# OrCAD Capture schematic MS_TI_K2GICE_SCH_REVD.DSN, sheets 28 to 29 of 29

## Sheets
28 P28_POWER ORING & OVP: size C; title: POWER ORING & OVP CIRCUIT
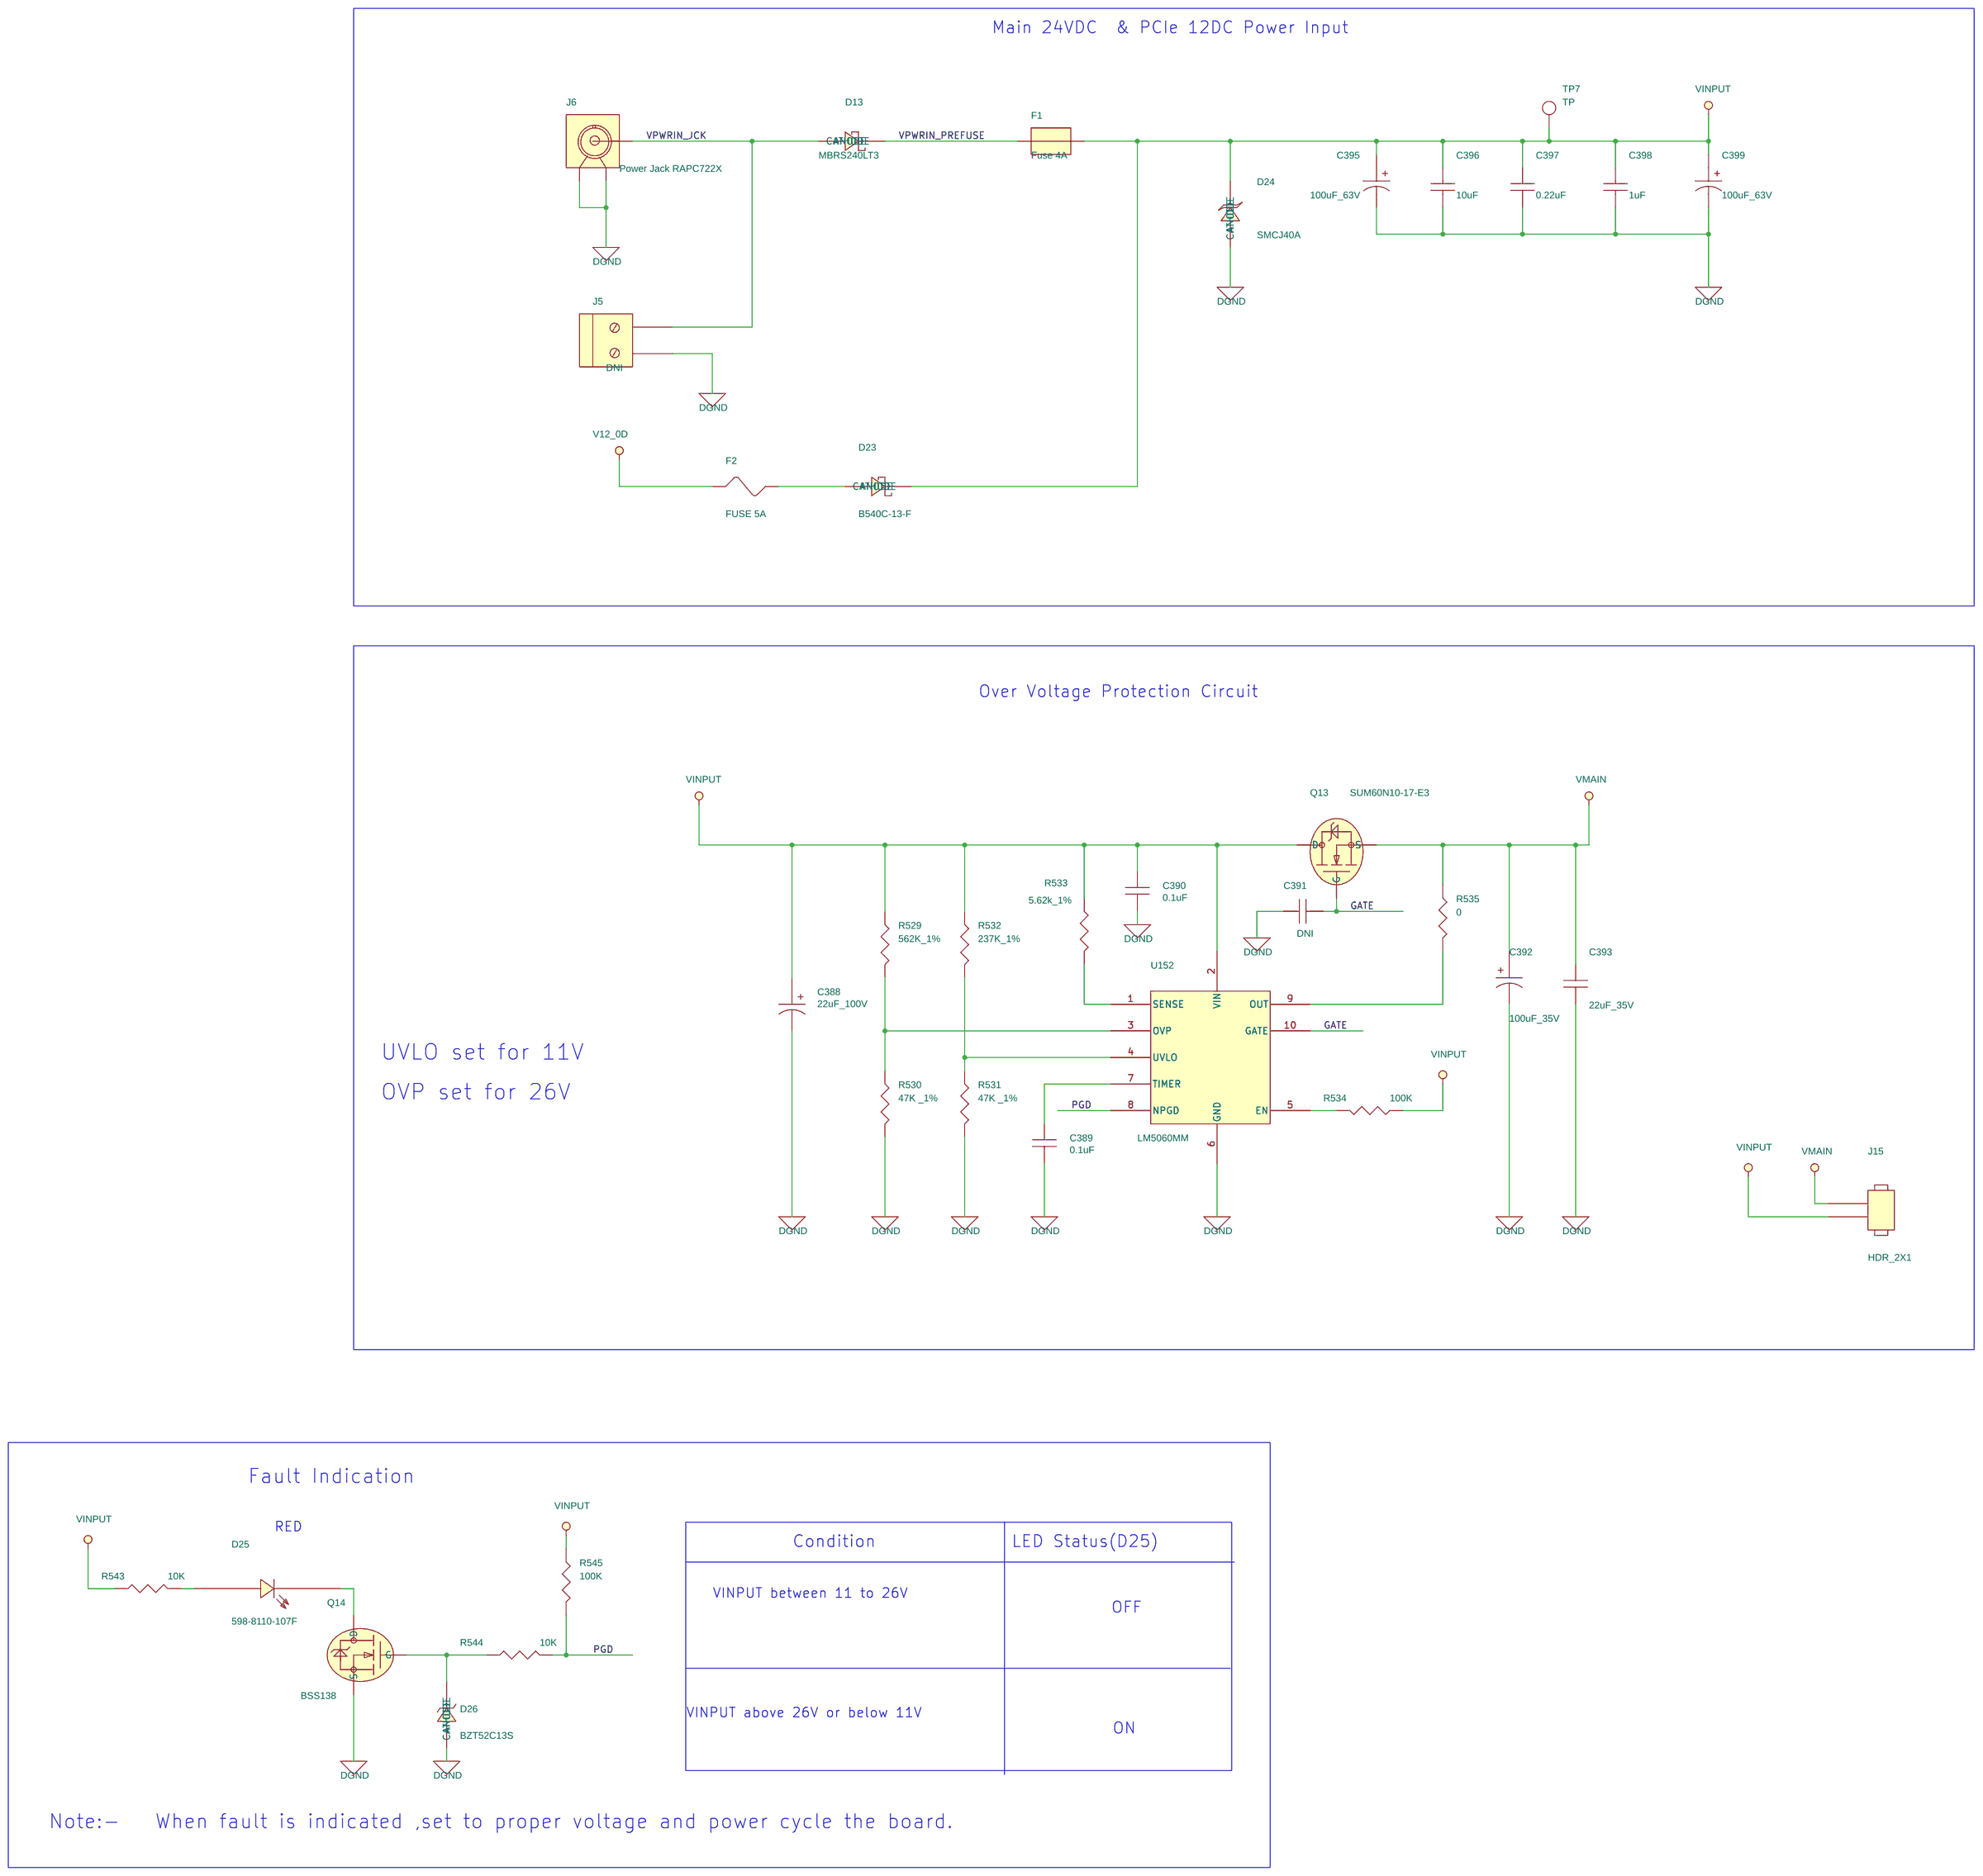
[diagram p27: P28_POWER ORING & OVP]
29 P29_HARDWARE SCHEMATICS: size C; title: HARDWARE SCHEMATICS
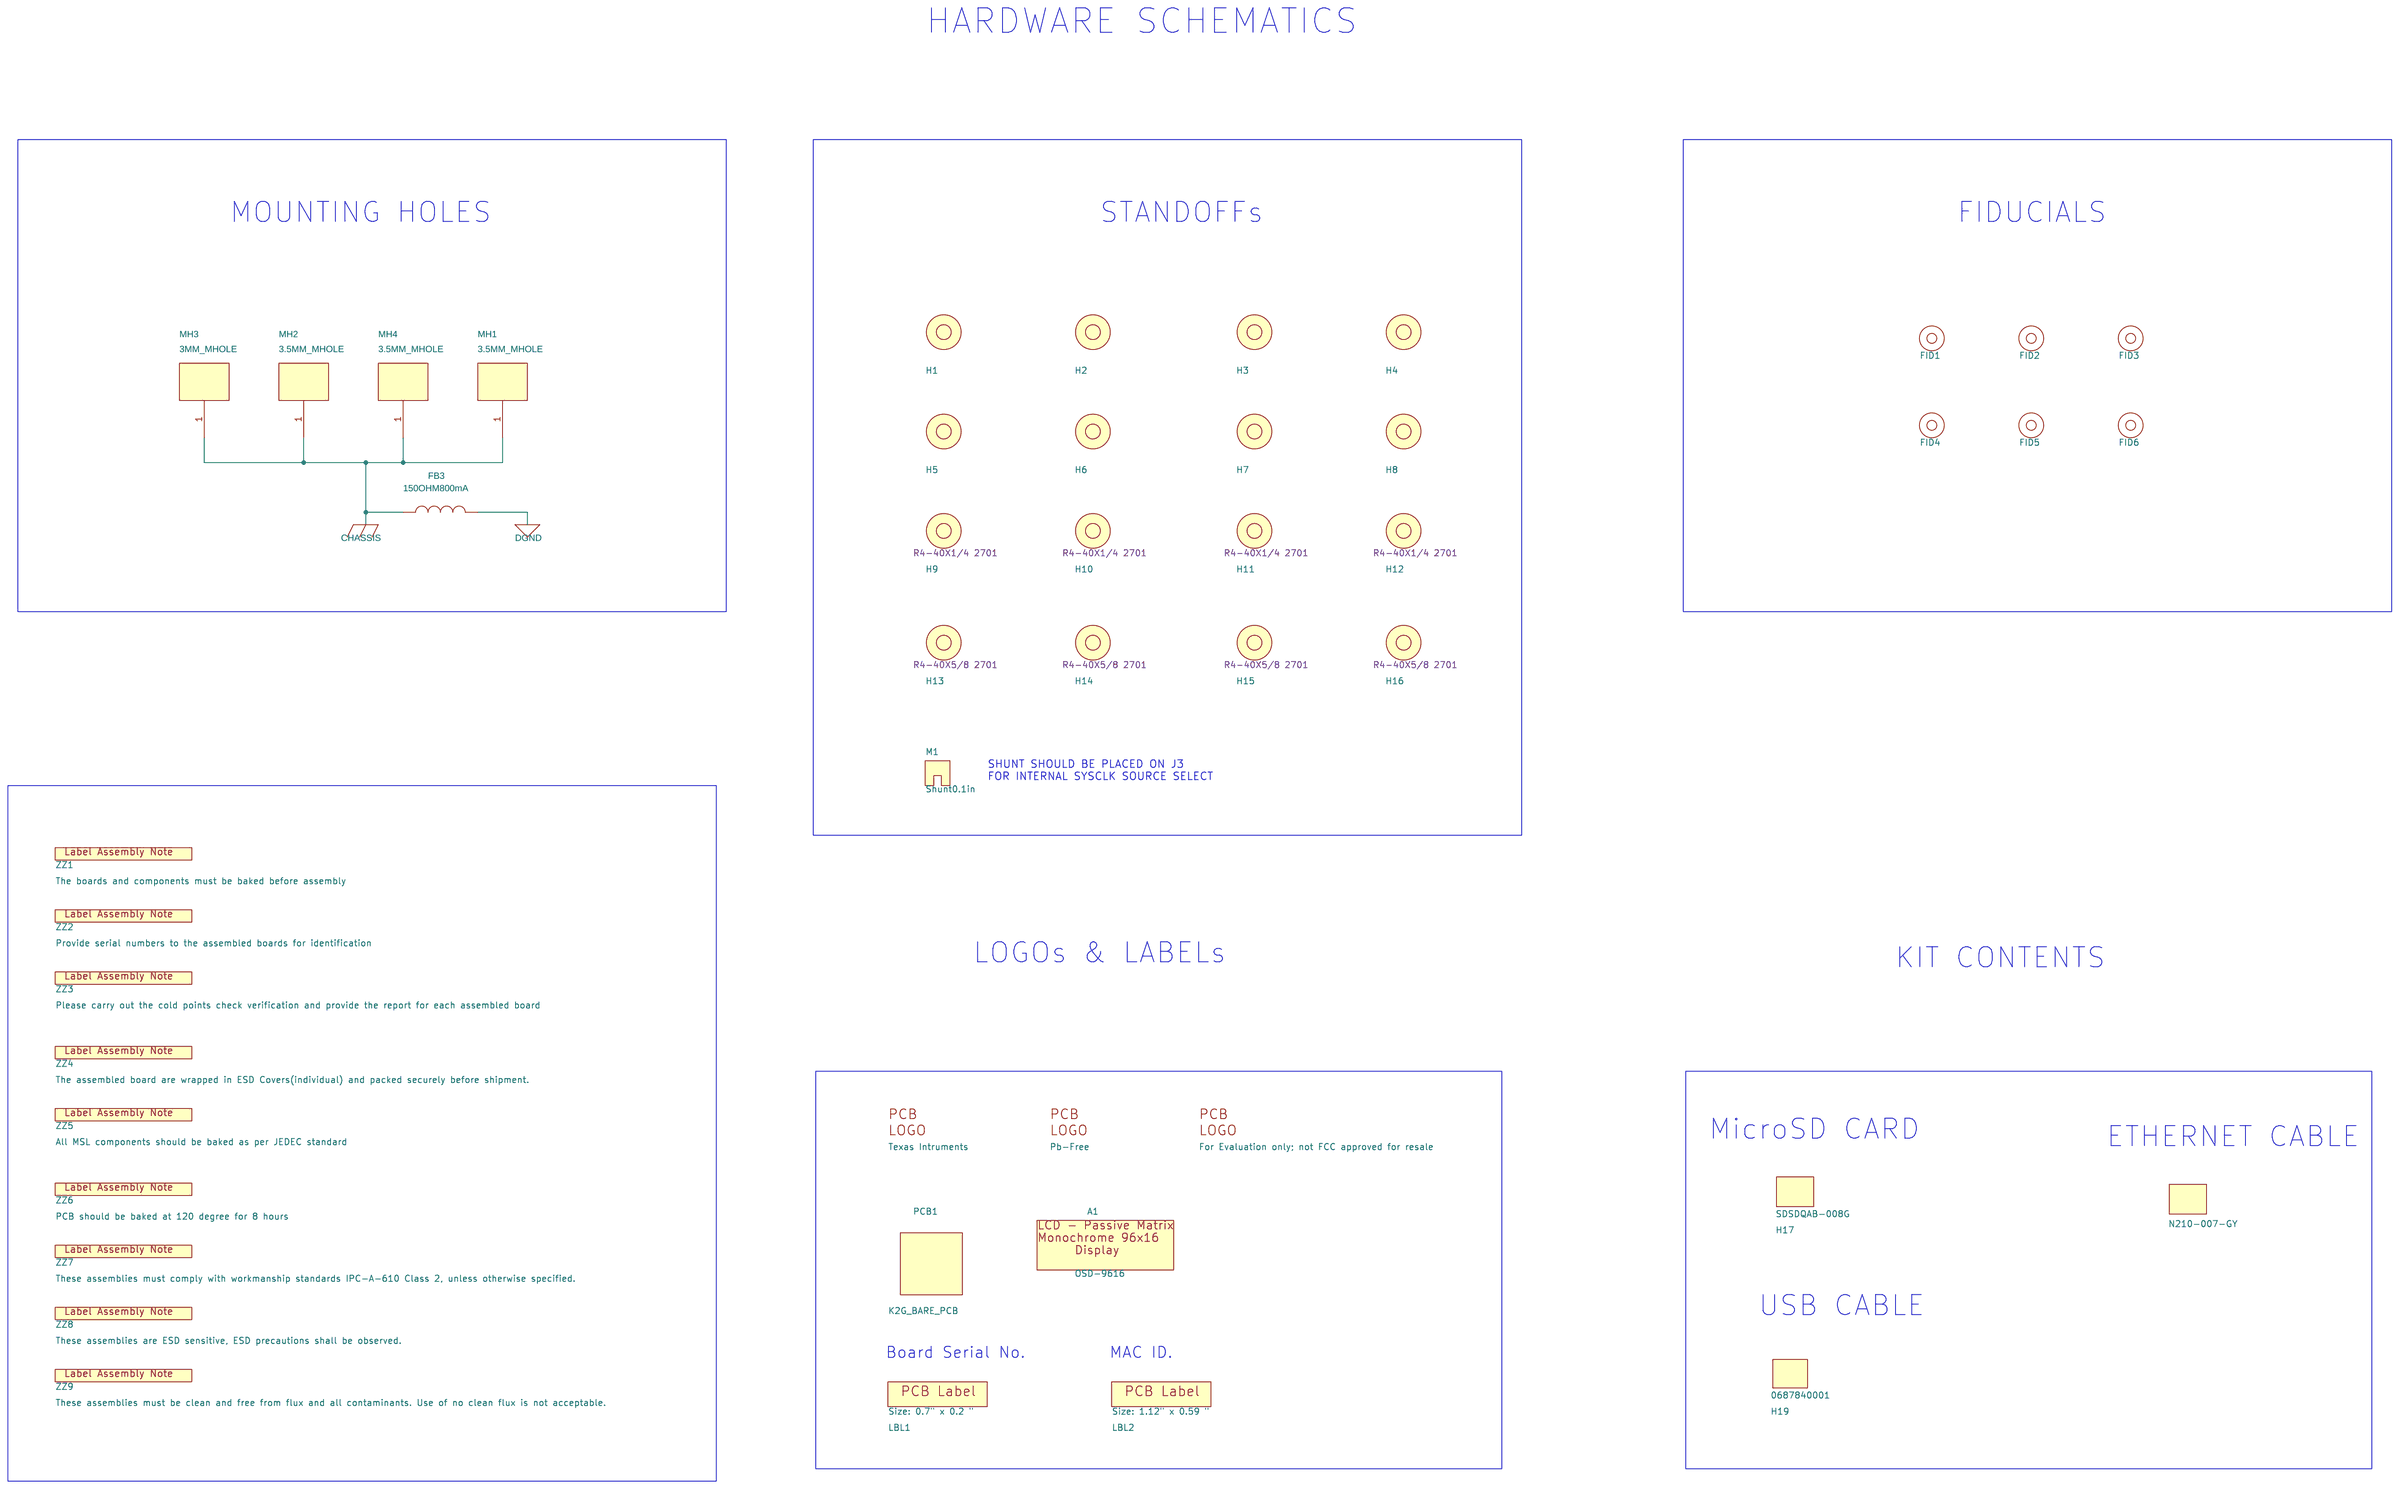
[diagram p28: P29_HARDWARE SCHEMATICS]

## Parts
sheet P28_POWER ORING & OVP
C388  22uF_100V  [CAPAE_GCASE]
C389  0.1uF  [CAP0603]
C390  0.1uF  [CAP0603]
C391  DNI  [SM-7351-CAP-0402]
C392  100uF_35V  [CAPAE_D8CASE]
C393  22uF_35V  [CAP0805]
C395  100uF_63V  [CAPAE_CASE1213]
C396  10uF  [CAP1210]
C397  0.22uF  [CAP1206]
C398  1uF  [CAP1206]
C399  100uF_63V  [CAPAE_CASE1213]
D13  MBRS240LT3  [DIO_SMB]
D23  B540C-13-F  [DIO_SMC]
D24  SMCJ40A  [DIO_SMC]
D25  598-8110-107F  [LED_0805]
D26  BZT52C13S  [DIO_SOD323]
F1  Fuse 4A  [smdfuseblk]
F2  FUSE 5A  [FUSE-RGEF600]
J5  DNI  [conn_osttc02]
J6  Power Jack RAPC722X  [RAPC712]
J15  HDR_2X1  [HDR_2X1_100_S_T]
Q13  SUM60N10-17-E3  [D2PAK-3]
Q14  BSS138  [TO_SOT23-123]
R529  562K_1%  [RES0402]
R530  47K _1%  [RES0402]
R531  47K _1%  [RES0402]
R532  237K_1%  [RES0402]
R533  5.62k_1%  [RES0603]
R534  100K  [RES0402]
R535  0  [RES0402]
R543  10K  [RES1206]
R544  10K  [SM-7351-RES-0402]
R545  100K  [SM-7351-RES-0402]
TP7  TP  [TH_TP_5002]
U152  LM5060MM  [MSOP10_19-68_120X120]
sheet P29_HARDWARE SCHEMATICS
A1  OSD-9616  [-]
FB3  150OHM800mA  [sm-7351-ind-0805]
FID1  Fiducial  [Fiducial10-20]
FID2  Fiducial  [Fiducial10-20]
FID3  Fiducial  [Fiducial10-20]
FID4  Fiducial  [Fiducial10-20]
FID5  Fiducial  [Fiducial10-20]
FID6  Fiducial  [Fiducial10-20]
H1  3482  [Keystone_1902C]
H2  3482  [Keystone_1902C]
H3  3482  [Keystone_1902C]
H4  3482  [Keystone_1902C]
H5  720  [Keystone_1902C]
H6  720  [Keystone_1902C]
H7  720  [Keystone_1902C]
H8  720  [Keystone_1902C]
H9  R4-40X1/4 2701  [Keystone_1902C]
H10  R4-40X1/4 2701  [Keystone_1902C]
H11  R4-40X1/4 2701  [Keystone_1902C]
H12  R4-40X1/4 2701  [Keystone_1902C]
H13  R4-40X5/8 2701  [Keystone_1902C]
H14  R4-40X5/8 2701  [Keystone_1902C]
H15  R4-40X5/8 2701  [Keystone_1902C]
H16  R4-40X5/8 2701  [Keystone_1902C]
H17  SDSDQAB-008G  [Keystone_1902C]
H18  N210-007-GY  [Keystone_1902C]
H19  0687840001  [Keystone_1902C]
LBL1  Size: 0.7" x 0.2 "  [Label_650x200]
LBL2  Size: 1.12" x 0.59 "  [Label_650x200]
LOGO1  Texas Intruments  [TI_Stacked_Overlay_Small]
LOGO2  Pb-Free  [Pb-Free_Overlay_Small]
LOGO3  For Evaluation only; not FCC approved for resale  [FCC_disclaimer]
M1  Shunt0.1in  [DNP]
MH1  3.5MM_MHOLE  [MH163X138PL]
MH2  3.5MM_MHOLE  [MH163X138PL]
MH3  3MM_MHOLE  [MH163X138PL]
MH4  3.5MM_MHOLE  [MH163X138PL]
PCB1  K2G_BARE_PCB  [-]
ZZ1  The boards and components must be baked before assembly  [AssemblyNoteLabel]
ZZ2  Provide serial numbers to the assembled boards for identification  [AssemblyNoteLabel]
ZZ3  Please carry out the cold points check verification and provide the report for each assembled board  [AssemblyNoteLabel]
ZZ4  The assembled board are wrapped in ESD Covers(individual) and packed securely before shipment.  [AssemblyNoteLabel]
ZZ5  All MSL components should be baked as per JEDEC standard  [AssemblyNoteLabel]
ZZ6  PCB should be baked at 120 degree for 8 hours  [AssemblyNoteLabel]
ZZ7  These assemblies must comply with workmanship standards IPC-A-610 Class 2, unless otherwise specified.  [AssemblyNoteLabel]
ZZ8  These assemblies are ESD sensitive, ESD precautions shall be observed.  [AssemblyNoteLabel]
ZZ9  These assemblies must be clean and free from flux and all contaminants. Use of no clean flux is not acceptable.  [AssemblyNoteLabel]

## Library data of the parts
C388 = CAP_POL: Crtd /date: VASANTHA/170516; DescriptiveText: CAP ELECTROLYTIC 22uF 100V 20% GCASE_103103; Mfr: PANASONIC-ECG; MfrNum: EEE-HA2A220P; Mistral part number: NSPN00373; Part_type: CAPACITORS\ELECTROLYTIC
C389 C390 = CAP: Crtd /date: VASANTHA/170516; DescriptiveText: CAP CERAMIC 0.1uF 100V 10% X7R 0603; Mfr: YAGEO AMERICA; MfrNum: CC0603KRX7R0BB104; Mistral part number: NSPN00374; Part_type: CAPACITORS\CERAMIC
C391 = 1C_0.01uFCapacitor16V10%0402
C392 = CAP_POL: Crtd /date: VASANTHA/170516; DescriptiveText: CAP ELECTROLYTIC 100uF 35V 20% D8CASE_6666; Mfr: PANASONIC-ECG; MfrNum: EEE-FK1V101XP; Mistral part number: NSPN00370; Part_type: CAPACITORS\ELECTROLYTIC
C393 = CAP: Crtd /date: VASANTHA/170516; DescriptiveText: CAP CERAMIC 22uF 35V 20% X5R 0805; Mfr: TDK CORPORATION; MfrNum: C2012X5R1V226M125AC; Mistral part number: NSPN00375; Part_type: CAPACITORS\CERAMIC
C395 C399 = CAP_POL: Crtd /date: VASANTHA/170516; DescriptiveText: CAP ELECTROLYTIC 100uF 63V 20% RADIAL CAN CASE1213; Mfr: VISHAY; MfrNum: MAL214699806E3; Mistral part number: NSPN00372; Part_type: CAPACITORS\ELECTROLYTIC
C396 = CAP: Crtd /date: VASANTHA/170516; DescriptiveText: CAP CERAMIC 10uF 63V 10% X7R 1210; Mfr: MURATA; MfrNum: GRM32ER71J106KA12L; Mistral part number: NSPN00367; Part_type: CAPACITORS\CERAMIC
C397 = CAP: Crtd /date: VASANTHA/170516; DescriptiveText: CAP CERAMIC 0.22uF 100V 10% X7R 1206; Mfr: MURATA; MfrNum: GRM31MR72A224KA01L; Mistral part number: NSPN00369; Part_type: CAPACITORS\CERAMIC
C398 = CAP: Crtd /date: VASANTHA/170516; DescriptiveText: CAP CERAMIC 1uF 100V 10% X7R 1206; Mfr: TDK CORPORATION; MfrNum: C3216X7R2A105K160AA; Mistral part number: NSPN00371; Part_type: CAPACITORS\CERAMIC
D13 = DIODE_SCHOTTKY: DIODE SCHOTTKY 40V 2A SMB; Crtd /date: VASANTHA/100616; Custom_Duty: 15%; Customs_HS_Code: 85412900; DescriptiveText: DIODE SCHOTTKY 40V 2A SMB; Distributor_name: DIGIKEY; Distributor_part_number: MBRS240LT3OSTR-ND; Height: 2.62MM; Mfr: ON SEMICONDUCTOR; MfrNum: MBRS240LT3G; Mfr_name: ON SEMICONDUCTOR; Mfr_part_number: MBRS240LT3G; Mistral Part No: 130009030216; Mistral part number: NSPN00396; Package: SMB; Part_type: DIODE\SCHOTTKY; Project: G4SLIM; Voltage: 40V; Datasheet: Y:\MIS_DATABASE\DATASHEETS\DISCRETES\DIODES\B5.PDF
D23 = DIODE_SCHOTTKY: Crtd /date: VASANTHA/170516; DescriptiveText: DIODE SCHOTTKY 40V 5A SMC; Mfr: DIODES INC; Mistral part number: NSPN00377; Part_type: DIODE\SCHOTTKY
D24 = DIODE_TVS: Crtd /date: VASANTHA/170516; DescriptiveText: DIODE TVS 1500W 40V SMC; Mfr: BOURNS; Mistral part number: NSPN00378; Part_type: DIODE\TVS
D25 = LED_598-8170-107F: Crtd /date: VASANTHA/170516; DescriptiveText: LED ALINGAP RED CLEAR 0805 SMD; Mfr: DIALIGHT; MfrNum: 5988110107F; Mistral part number: NSPN00379; Part_type: OPTO\LED
D26 = DIODE_ZENER: Crtd /date: VASANTHA/170516; DescriptiveText: DIODE ZENER 13V 200mW SOD323; Mfr: DIODES INC; MfrNum: BZT52C13S-7-F; Mistral part number: NSPN00376; Part_type: DIODE\ZENER
F1 = 1P_Fuse_4A
F2 = Fuse_RGEF600-2
J5 = 2C_Conn_LeadScrewDown_2pin
J6 = 2J_Conn_PwrJack_RAPC722
J15 = HEADER_2X1: Crtd /date: VASANTHA/170516; DescriptiveText: CON HDR 2X1 2.54MM PITCH ST TH; Mfr: MOLEX; MfrNum: 0022032021; Mistral part number: NSPN00390; Part_type: CONNECTOR\HEADER
Q13 = MOSFET_IRFZ24NS: Crtd /date: VASANTHA/170516; DescriptiveText: IC POWER MOSFET N-CHANNEL D2PAK; Mfr: VISHAY; Mistral part number: NSPN00388; Part_type: ICS\POWER\MOSFET
Q14 = MOSFET_BSS138: Crtd /date: VASANTHA/170516; DescriptiveText: IC MOSFET N-CHANNEL 50V 200mA SOT23-3; Mfr: DIODES INC; MfrNum: BSS138-7-F; Mistral part number: NSPN00386; Part_type: ICS\POWER\MOSFET
R529 = RESISTOR: Crtd /date: VASANTHA/170516; DescriptiveText: RES 562K 1/16W 1% 0402; Mfr: PANASONIC-ECG; MfrNum: ERJ-2RKF5623X; Mistral part number: NSPN00360; Part_type: RESISTORS\FIXED
R530 R531 = RESISTOR: Crtd /date: VASANTHA/170516; DescriptiveText: RES 47K 1/16W 1% 0402; Mfr: YAGEO AMERICA; MfrNum: RC0402FR-0747KL; Mistral part number: NSPN00358; Part_type: RESISTORS\FIXED
R532 = RESISTOR: Crtd /date: VASANTHA/170516; DescriptiveText: RES 237K 1/16W 1% 0402; Mfr: STACKPOLE ELECTRONICS; MfrNum: RMCF0402FT237K; Mistral part number: NSPN00365; Part_type: RESISTORS\FIXED
R533 = RESISTOR: Crtd /date: VASANTHA/170516; DescriptiveText: RES 5.62K 1/10W 1% 0603; Mfr: VISHAY; MfrNum: CRCW06035K62FKEA; Mistral part number: NSPN00362; Part_type: RESISTORS\FIXED
R534 = RESISTOR: Crtd /date: VASANTHA/170516; DescriptiveText: RES 100K 1/16W 5% 0402; Mfr: PANASONIC-ECG; MfrNum: ERJ-2GEJ104X; Mistral part number: NSPN00355; Part_type: RESISTORS\FIXED
R535 = RESISTOR: Crtd /date: VASANTHA/170516; DescriptiveText: RES 0E 1/10W 5% 0402; Mfr: PANASONIC-ECG; MfrNum: ERJ-2GE0R00X; Mistral part number: NSPN00364; Part_type: RESISTORS\FIXED
R543 = RESISTOR: Crtd /date: VASANTHA/170516; DescriptiveText: RES 10K 2/3W 5% 1206; Mfr: PANASONIC; MfrNum: ERJ-P08J103V; Mistral part number: NSPN00366; Part_type: RESISTORS\FIXED
R544 = 1R_10KOhmResistor1_16W0402
R545 = 1R_100KOhmResistor1_16W0402
TP7 = 2H_TestPointThroughHole
U152 = LM5060_MSOP10: Crtd /date: VASANTHA/170516; DescriptiveText: IC CONTROLLER HIGH-SIDE PROTECTION VSSOP10; Mfr: TEXAS INSTRUMENTS; MfrNum: LM5060MM/NOPB; Mistral part number: NSPN00387; Part_type: ICS\POWER\MANAGEMENT
A1 = LCD_OSD9616P0899-10: MfrNum: OSD9616P0992-10
FB3 = FerBead_180ohm200mA
FID1-FID6 = Fiducial
H1-H4 = 3482: DescriptiveText: Round Standoff Threaded #4-40 Aluminum 1.000" (25.40mm) 1"
H5-H8 = 720: DescriptiveText: Bumper Cylindrical, Recessed Center 0.500" Dia (12.70mm) Rubber, Buna S Black
H9-H12 = PMSSS_440_0025_PH: DescriptiveText: Screw #4-40 1/4in long zinc phillips; Mfr: APM Hexseal; PartName: Screw4-40PanHead1/4in; Vendor: Digikey
H13-H16 = PMSSS_440_0063_PH: DescriptiveText: Screw #4-40 5/8in long zinc phillips; Mfr: APM Hexseal; PartName: Screw4-40PanHead5/8in; Vendor: Digikey
H17 = uSD_card: Sandisk  8Gb Class 4 Microsdhc Memory Card; Descriptive_Text: Sandisk  8Gb Class 4 Microsdhc Memory Card; Mfr_name: SanDisk
H18 = RJ45_Cable
H19 = USB_Cable: USB 2.0 Cable A Male to Micro B Male 3.28' (1.00m) Shielded; Mfr_name: Molex, LLC
LBL1 LBL2 = THT-14-423-10: Serail Number Label
LOGO1 = TI_Logo
LOGO2 = Pb-Free
LOGO3 = FCC_disclaimer
M1 = 2H_Shunt0.1in
MH1-MH4 = Mounthole_3mm
PCB1 = Bare_PCB
ZZ1-ZZ9 = AssemblyNoteLabel_0

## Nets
DGND: C388.2 C389.2 C390.2 C391.1 C392.2 C393.2 C395.2 C396.2 C397.2 C398.2 C399.2 D24.2(ANODE) D26.2(ANODE) FB3.2 J5.2 J6.2 J6.3 Q14.2(S) R530.2 R531.2 U152.6(GND) ; also on sheet 4 5 6 7 8 9 10 11 12 13 14 15 16 17 18 19 20 21 22 23 24 25 26 27
V12_0D: F2.1 ; also on sheet 25
VINPUT: C388.1 C390.1 C395.1 C396.1 C397.1 C398.1 C399.1 D23.1(CATHODE) D24.1(CATHODE) F1.2 J15.1 Q13.4(D) R529.1 R532.1 R533.1 R534.1 R543.1 R545.2(P2) TP7.1 U152.2(VIN)
CHASSIS: FB3.1 MH1.1 MH2.1 MH3.1 MH4.1
GATE: C391.2 Q13.1(G) U152.10(GATE)
PGD: R544.1(P1) R545.1(P1) U152.8(NPGD)
VMAIN: C392.1 C393.1 J15.2 Q13.3(S) R535.1 ; also on sheet 4 24
VPWRIN_JCK: D13.2(ANODE) J5.1 J6.1
VPWRIN_PREFUSE: D13.1(CATHODE) F1.1
N33658210: D23.2(ANODE) F2.2
N33658699: R534.2 U152.5(EN)
N33658710: R533.2 U152.1(SENSE)
N33658738: R535.2 U152.9(OUT)
N33658755: C389.1 U152.7(TIMER)
N33658854: R529.2 R530.1 U152.3(OVP)
N33658856: R531.1 R532.2 U152.4(UVLO)
N33857836: D25.1 Q14.3(D)
N33857874: D26.1(CATHODE) Q14.1(G) R544.2(P2)
N33857887: D25.2 R543.2

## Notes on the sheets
sheet 28
- Main 24VDC  & PCIe 12DC Power Input
- Over Voltage Protection Circuit
- UVLO set for 11V
- OVP set for 26V
- Fault Indication
- RED
- Condition
- LED Status(D25)
- VINPUT between 11 to 26V
- OFF
- VINPUT above 26V or below 11V
- ON
- Note:-
- When fault is indicated ,set to proper voltage and power cycle the board.
sheet 29
- HARDWARE SCHEMATICS
- MOUNTING HOLES
- STANDOFFs
- FIDUCIALS
- SHUNT SHOULD BE PLACED ON J3
  FOR INTERNAL SYSCLK SOURCE SELECT
- LOGOs & LABELs
- KIT CONTENTS
- MicroSD CARD
- ETHERNET CABLE
- USB CABLE
- Board Serial No.
- MAC ID.
